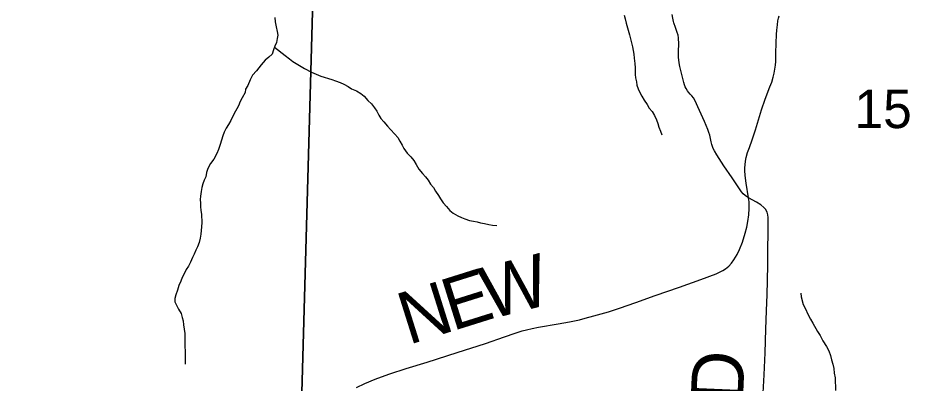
# Model space of a CAD drawing. Extents: x -3.3 to 34, y 0 to 56.8.
# Drawn here: x -1.696 to -0.715, y 29.871 to 30.269 of the extents above; entities that cross this region are included whole.
import ezdxf

# ---------------------------------------------------------------- set-up
doc = ezdxf.new("R2010")
doc.units = 0
for name, color, linetype in [('GM_X_Corporation', 7, 'Continuous'), ('GM_X_County_Road', 7, 'Continuous'), ('GM_X_Section_Text', 7, 'Continuous'), ('GM_X_Township_Road', 7, 'Continuous'), ('GM_X_Township_Road_Text', 7, 'Continuous'), ('GT_Project_Soil_Layers', 7, 'Continuous'), ('SH_Masking', 7, 'Continuous')]:
    doc.layers.add(name, color=color, linetype=linetype)

msp = doc.modelspace()

# ---------------------------------------------------------------- linework, layer by layer
at = {"layer": 'GM_X_Corporation'}
for points in [[(-2.39277, 30.73672), (-1.36367, 30.70347), (-1.39177, 29.70668), (-2.4143, 29.73246)], [(-0.36109, 30.66979), (-0.38619, 29.67495), (-1.39177, 29.70668), (-1.36367, 30.70347)]]:
    msp.add_lwpolyline(points, close=True, dxfattribs=at)
at = {"layer": 'GM_X_County_Road'}
for points in [[(-0.90153, 30.07382), (-0.90399, 30.0897), (-0.90473, 30.09504), (-0.90514, 30.0985), (-0.90547, 30.10301), (-0.90556, 30.10647), (-0.90543, 30.10958), (-0.90494, 30.11372), (-0.90418, 30.11783), (-0.90263, 30.12321), (-0.90068, 30.12853), (-0.89758, 30.13696), (-0.89413, 30.14757), (-0.88731, 30.16965), (-0.88352, 30.18103), (-0.87826, 30.19442), (-0.87638, 30.19966), (-0.87489, 30.20486), (-0.87366, 30.20947), (-0.87284, 30.21357), (-0.87218, 30.21794), (-0.87194, 30.22221), (-0.87175, 30.2312), (-0.87149, 30.24185), (-0.8712, 30.25147), (-0.87087, 30.25599), (-0.87021, 30.26175), (-0.86955, 30.2661), (-0.86898, 30.26914), (-0.86842, 30.27159)], [(-1.32802, 29.86761), (-1.31881, 29.872), (-1.30774, 29.87671), (-1.30062, 29.87935), (-1.29163, 29.88252), (-1.27376, 29.88822), (-1.25097, 29.89513), (-1.21837, 29.90564), (-1.18757, 29.91557), (-1.16693, 29.92261), (-1.15542, 29.92654), (-1.14766, 29.92907), (-1.14293, 29.93034), (-1.13673, 29.93171), (-1.13008, 29.93305), (-1.10848, 29.93667), (-1.0961, 29.93897), (-1.08556, 29.94125), (-1.07933, 29.94281), (-1.06979, 29.94543), (-1.05369, 29.95004), (-1.04207, 29.95376), (-1.02409, 29.96012), (-1.00324, 29.96748), (-0.97672, 29.97684), (-0.95361, 29.985), (-0.93684, 29.99114), (-0.93301, 29.99289), (-0.92951, 29.99475), (-0.92654, 29.99662), (-0.92299, 29.9995), (-0.91997, 30.00287), (-0.91767, 30.00626), (-0.91405, 30.01207), (-0.91142, 30.01755), (-0.90824, 30.02544), (-0.90528, 30.03531), (-0.90353, 30.04199), (-0.90221, 30.04824), (-0.90133, 30.05537), (-0.90095, 30.06225), (-0.90103, 30.06964), (-0.90153, 30.07382)]]:
    msp.add_lwpolyline(points, dxfattribs=at)
at = {"layer": 'GM_X_Township_Road'}
msp.add_lwpolyline([(-0.88571, 29.86187), (-0.88477, 29.88143), (-0.8836, 29.90535), (-0.88282, 29.93091), (-0.8822, 29.95101), (-0.88142, 29.96855), (-0.88088, 29.98343), (-0.88063, 30.00135), (-0.88044, 30.01927), (-0.88027, 30.03477), (-0.88006, 30.04878), (-0.88013, 30.05231), (-0.88051, 30.05535), (-0.88142, 30.05828), (-0.88305, 30.06132), (-0.8848, 30.06327), (-0.88839, 30.06637), (-0.89288, 30.0691), (-0.90153, 30.07382), (-0.90529, 30.0764), (-0.90727, 30.07813), (-0.90916, 30.08026), (-0.91368, 30.08693), (-0.91936, 30.09541), (-0.92827, 30.10873), (-0.93612, 30.12046), (-0.93866, 30.12482), (-0.9399, 30.12745), (-0.9408, 30.12958), (-0.94146, 30.13172), (-0.94228, 30.13468), (-0.94385, 30.14208), (-0.94467, 30.14496), (-0.94582, 30.14824), (-0.9496, 30.15688), (-0.95494, 30.1687), (-0.96004, 30.17998), (-0.96152, 30.1826), (-0.96333, 30.18482), (-0.96513, 30.18664), (-0.96678, 30.18861), (-0.96801, 30.19025), (-0.96957, 30.19263), (-0.97048, 30.19444), (-0.9713, 30.19666), (-0.97204, 30.19938), (-0.97413, 30.20777), (-0.97633, 30.21657), (-0.97705, 30.2205), (-0.97755, 30.22387), (-0.97771, 30.2265), (-0.97759, 30.2334), (-0.97746, 30.24097), (-0.97771, 30.24779), (-0.97821, 30.25075), (-0.97902, 30.25355), (-0.98088, 30.25884), (-0.98269, 30.264), (-0.98323, 30.26555), (-0.98407, 30.26928), (-0.98451, 30.27305)], dxfattribs=at)
at = {"layer": 'GT_Project_Soil_Layers'}
for points in [[(-1.41659, 30.27001), (-1.41615, 30.26508), (-1.41532, 30.25978), (-1.41411, 30.25449), (-1.4133, 30.2507), (-1.41401, 30.2469), (-1.41471, 30.24271), (-1.41655, 30.23889), (-1.41801, 30.2347), (-1.41947, 30.23012), (-1.42321, 30.22665), (-1.42734, 30.22356), (-1.43145, 30.21857), (-1.43667, 30.21204), (-1.44115, 30.20705), (-1.44336, 30.20208), (-1.44593, 30.19598), (-1.44853, 30.19214), (-1.44886, 30.18835), (-1.4522, 30.18261), (-1.45442, 30.1784), (-1.45625, 30.17382), (-1.46144, 30.16464), (-1.46438, 30.15777), (-1.46697, 30.15356), (-1.46958, 30.14973), (-1.47179, 30.14514), (-1.47326, 30.14133), (-1.47471, 30.13637), (-1.47616, 30.1318), (-1.47799, 30.12646), (-1.47982, 30.12188), (-1.48315, 30.11576), (-1.4865, 30.11116), (-1.48946, 30.10581), (-1.49092, 30.10124), (-1.49162, 30.09667), (-1.49346, 30.09285), (-1.49492, 30.08903), (-1.49601, 30.08522), (-1.49671, 30.08066), (-1.4974, 30.07572), (-1.49773, 30.07192), (-1.49768, 30.06813), (-1.49763, 30.06433), (-1.49719, 30.06016), (-1.49638, 30.056), (-1.49625, 30.04652), (-1.49689, 30.03816), (-1.49722, 30.03436), (-1.49792, 30.02979), (-1.49899, 30.02523), (-1.50083, 30.02065), (-1.50267, 30.01683), (-1.50451, 30.01263), (-1.50636, 30.00881), (-1.50857, 30.00384), (-1.51041, 29.99964), (-1.51301, 29.99581), (-1.51522, 29.99123), (-1.51744, 29.98702), (-1.51891, 29.98321), (-1.52112, 29.97862), (-1.52256, 29.97329), (-1.52439, 29.96833), (-1.52548, 29.96452), (-1.52543, 29.96073), (-1.52348, 29.95696), (-1.52153, 29.95281), (-1.51843, 29.94792), (-1.51762, 29.94376), (-1.51643, 29.93998), (-1.51599, 29.93582), (-1.51517, 29.93089), (-1.51473, 29.92635), (-1.51428, 29.89296)], [(-1.03666, 30.27235), (-1.03585, 30.26857), (-1.03464, 30.26365), (-1.03106, 30.25118), (-1.02986, 30.24664), (-1.02867, 30.24248), (-1.02785, 30.23794), (-1.02704, 30.23416), (-1.02623, 30.23), (-1.02579, 30.22583)], [(-1.417, 30.23761), (-1.40542, 30.22842), (-1.40082, 30.22507), (-1.39699, 30.22209), (-1.38437, 30.2143), (-1.37674, 30.21061), (-1.36682, 30.2062), (-1.36301, 30.20511), (-1.35844, 30.20366), (-1.35463, 30.20258), (-1.35082, 30.20111), (-1.34549, 30.19929), (-1.34167, 30.19745), (-1.33709, 30.19485), (-1.33326, 30.19225), (-1.32792, 30.19005), (-1.32333, 30.18708), (-1.3195, 30.18448), (-1.31564, 30.1796), (-1.31142, 30.17586), (-1.30833, 30.17173), (-1.30563, 30.16798), (-1.30367, 30.16383), (-1.30135, 30.16007), (-1.29827, 30.15632), (-1.29403, 30.15182), (-1.29095, 30.14807), (-1.28633, 30.1432), (-1.28287, 30.13946), (-1.28092, 30.13531), (-1.27821, 30.13118), (-1.27626, 30.12741), (-1.27278, 30.12253), (-1.26894, 30.11841), (-1.26547, 30.11428), (-1.26313, 30.11014), (-1.26003, 30.10487), (-1.25618, 30.10037), (-1.25271, 30.09663), (-1.25001, 30.09287), (-1.2473, 30.08873), (-1.24422, 30.08498), (-1.24189, 30.08122), (-1.23879, 30.07633), (-1.23646, 30.07257), (-1.23375, 30.06843), (-1.22991, 30.06432), (-1.22644, 30.06019), (-1.2226, 30.05721), (-1.21763, 30.05424), (-1.21382, 30.0524), (-1.21001, 30.05093), (-1.20505, 30.04911), (-1.20049, 30.04842), (-1.19669, 30.04771), (-1.19288, 30.04662), (-1.1887, 30.04592), (-1.18414, 30.04485), (-1.17996, 30.04415), (-1.1754, 30.04384)], [(-1.02579, 30.22583), (-1.02533, 30.21976), (-1.02489, 30.21522), (-1.02479, 30.20801), (-1.02436, 30.20422), (-1.02355, 30.20006), (-1.02312, 30.19627), (-1.02155, 30.1925), (-1.01997, 30.18834), (-1.01764, 30.1842), (-1.01493, 30.18007), (-1.01184, 30.17518), (-1.00951, 30.17142), (-1.00642, 30.16767), (-1.00371, 30.16315), (-1.00175, 30.15863), (-1.00018, 30.15447), (-0.99899, 30.1507), (-0.99741, 30.14617), (-0.99584, 30.14239)], [(-0.84486, 29.96999), (-0.84443, 29.9662), (-0.84205, 29.95789), (-0.84009, 29.95374), (-0.83659, 29.94658), (-0.83425, 29.94206), (-0.83153, 29.93755), (-0.82648, 29.92851), (-0.82377, 29.924), (-0.82066, 29.91835), (-0.81678, 29.91234), (-0.81444, 29.90744), (-0.81248, 29.90253), (-0.81127, 29.89762), (-0.81008, 29.89308), (-0.80887, 29.88816), (-0.80843, 29.88324), (-0.80722, 29.87794), (-0.80703, 29.86428)]]:
    msp.add_lwpolyline(points, dxfattribs=at)

# ---------------------------------------------------------------- texts
at = {"layer": 'GM_X_Section_Text'}
msp.add_text('15', height=0.041856, rotation=0.00001, dxfattribs=at).set_placement((-0.78631, 30.14963))
at = {"layer": 'GM_X_Township_Road_Text'}
msp.add_text('RD', height=0.056818, rotation=87.53133, dxfattribs=at).set_placement((-0.9101, 29.79667))
at = {"layer": 'SH_Masking'}
for s, rotation, p in [('W', 14.32209, (-1.18394, 29.94125)), ('E', 17.44964, (-1.2237, 29.92873)), ('N', 17.50701, (-1.27137, 29.91369))]:
    msp.add_text(s, height=0.05682, rotation=rotation, dxfattribs=at).set_placement(p)

doc.saveas('drawing.dxf')
